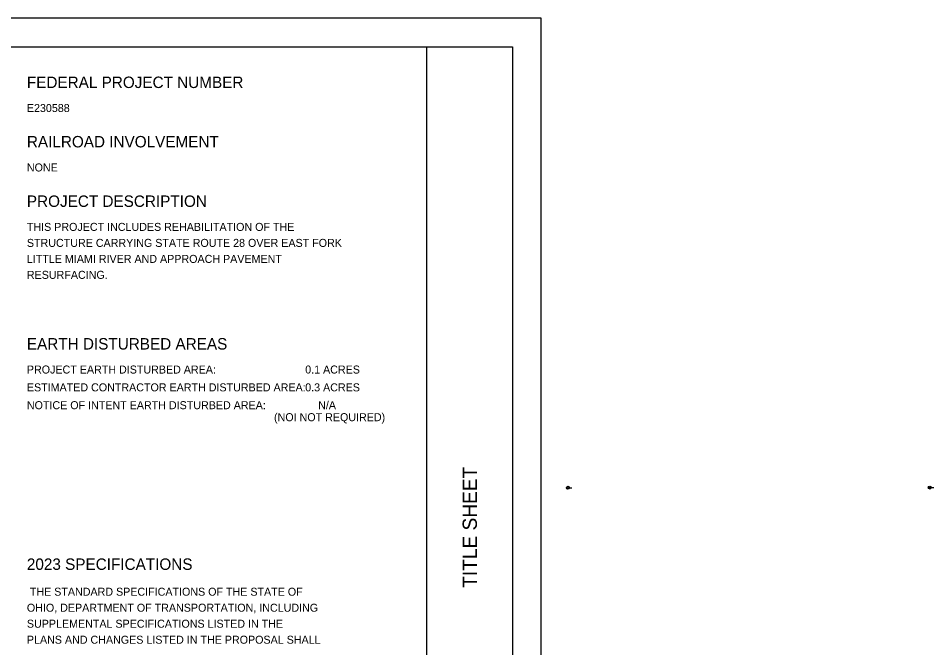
# Model space of a CAD drawing. Extents: x 0 to 40.9, y 0 to 22.
# Drawn here: x 24.85 to 40.87, y 10.99 to 22 of the extents above; entities that cross this region are included whole.
import ezdxf

# ---------------------------------------------------------------- set-up
doc = ezdxf.new("R2010")
doc.units = 0
for name, color, linetype in [('GM_X_Section', 7, 'Continuous'), ('SH_Border', 7, 'Continuous'), ('SH_Cut_Line', 7, 'Continuous'), ('SH_Data', 7, 'Continuous'), ('SH_Text', 7, 'Continuous')]:
    doc.layers.add(name, color=color, linetype=linetype)

msp = doc.modelspace()

# ---------------------------------------------------------------- linework, layer by layer
at = {"layer": 'GM_X_Section'}
for p, q in [((34.443, 13.785), (34.495, 13.785)), ((34.469, 13.785), (34.537, 13.785)), ((40.775, 13.788), (40.827, 13.788)), ((40.801, 13.788), (40.869, 13.788))]:
    msp.add_line(p, q, dxfattribs=at)
for centre in [(34.469, 13.785), (40.801, 13.788)]:
    msp.add_circle(centre, 0.026, dxfattribs=at)
at = {"layer": 'SH_Data'}
msp.add_lwpolyline([(0, 0), (34, 0), (34, 22), (0, 22)], close=True, dxfattribs=at)
at = {"layer": 'SH_Text'}
msp.add_line((32, 0.5), (32, 21.5), dxfattribs=at)
msp.add_lwpolyline([(1.5, 21.5), (33.5, 21.5), (33.5, 0.5), (1.5, 0.5)], close=True, dxfattribs=at)

# ---------------------------------------------------------------- texts
at = {"layer": 'GM_X_Section'}
for s, p in [('1', (34.468, 13.792)), ('Drawing', (34.502, 13.792)), ('CUSTOM 1:5280', (34.502, 13.775)), ('2', (40.8, 13.794)), ('Drawing-1', (40.834, 13.794)), ('CUSTOM 1:5280', (40.834, 13.778))]:
    msp.add_text(s, height=0.00328, dxfattribs=at).set_placement(p)
at = {"layer": 'SH_Border'}
for s, height, p in [('FEDERAL PROJECT NUMBER', 0.2, (25, 20.78)), ('E230588', 0.14, (25, 20.36)), ('RAILROAD INVOLVEMENT', 0.2, (25, 19.741)), ('NONE', 0.14, (25, 19.32)), ('PROJECT DESCRIPTION', 0.2, (25, 18.7)), ('THIS PROJECT INCLUDES REHABILITATION OF THE ', 0.14, (25, 18.28)), ('STRUCTURE CARRYING STATE ROUTE 28 OVER EAST FORK ', 0.14, (25, 18)), ('LITTLE MIAMI RIVER AND APPROACH PAVEMENT ', 0.14, (25, 17.72)), ('RESURFACING.', 0.14, (25, 17.441)), ('EARTH DISTURBED AREAS', 0.2, (25, 16.204)), ('PROJECT EARTH DISTURBED AREA:', 0.14, (25, 15.784)), ('0.1 ACRES', 0.14, (29.871, 15.784)), ('ESTIMATED CONTRACTOR EARTH DISTURBED AREA:', 0.14, (25, 15.472)), ('0.3 ACRES', 0.14, (29.871, 15.472)), ('NOTICE OF INTENT EARTH DISTURBED AREA:', 0.14, (25, 15.16)), ('N/A', 0.14, (30.097, 15.16)), ('(NOI NOT REQUIRED)', 0.14, (29.325, 14.95)), ('2023 SPECIFICATIONS', 0.2, (25, 12.348)), (' THE STANDARD SPECIFICATIONS OF THE STATE OF', 0.14, (25, 11.896)), ('OHIO, DEPARTMENT OF TRANSPORTATION, INCLUDING', 0.14, (25, 11.616)), ('SUPPLEMENTAL SPECIFICATIONS LISTED IN THE', 0.14, (25, 11.336)), ('PLANS AND CHANGES LISTED IN THE PROPOSAL SHALL', 0.14, (25, 11.056))]:
    msp.add_text(s, height=height, dxfattribs=at).set_placement(p)
at = {"layer": 'SH_Cut_Line'}
msp.add_text('TITLE SHEET', height=0.25, rotation=90, dxfattribs=at).set_placement((32.875, 12.035))

doc.saveas('drawing.dxf')
